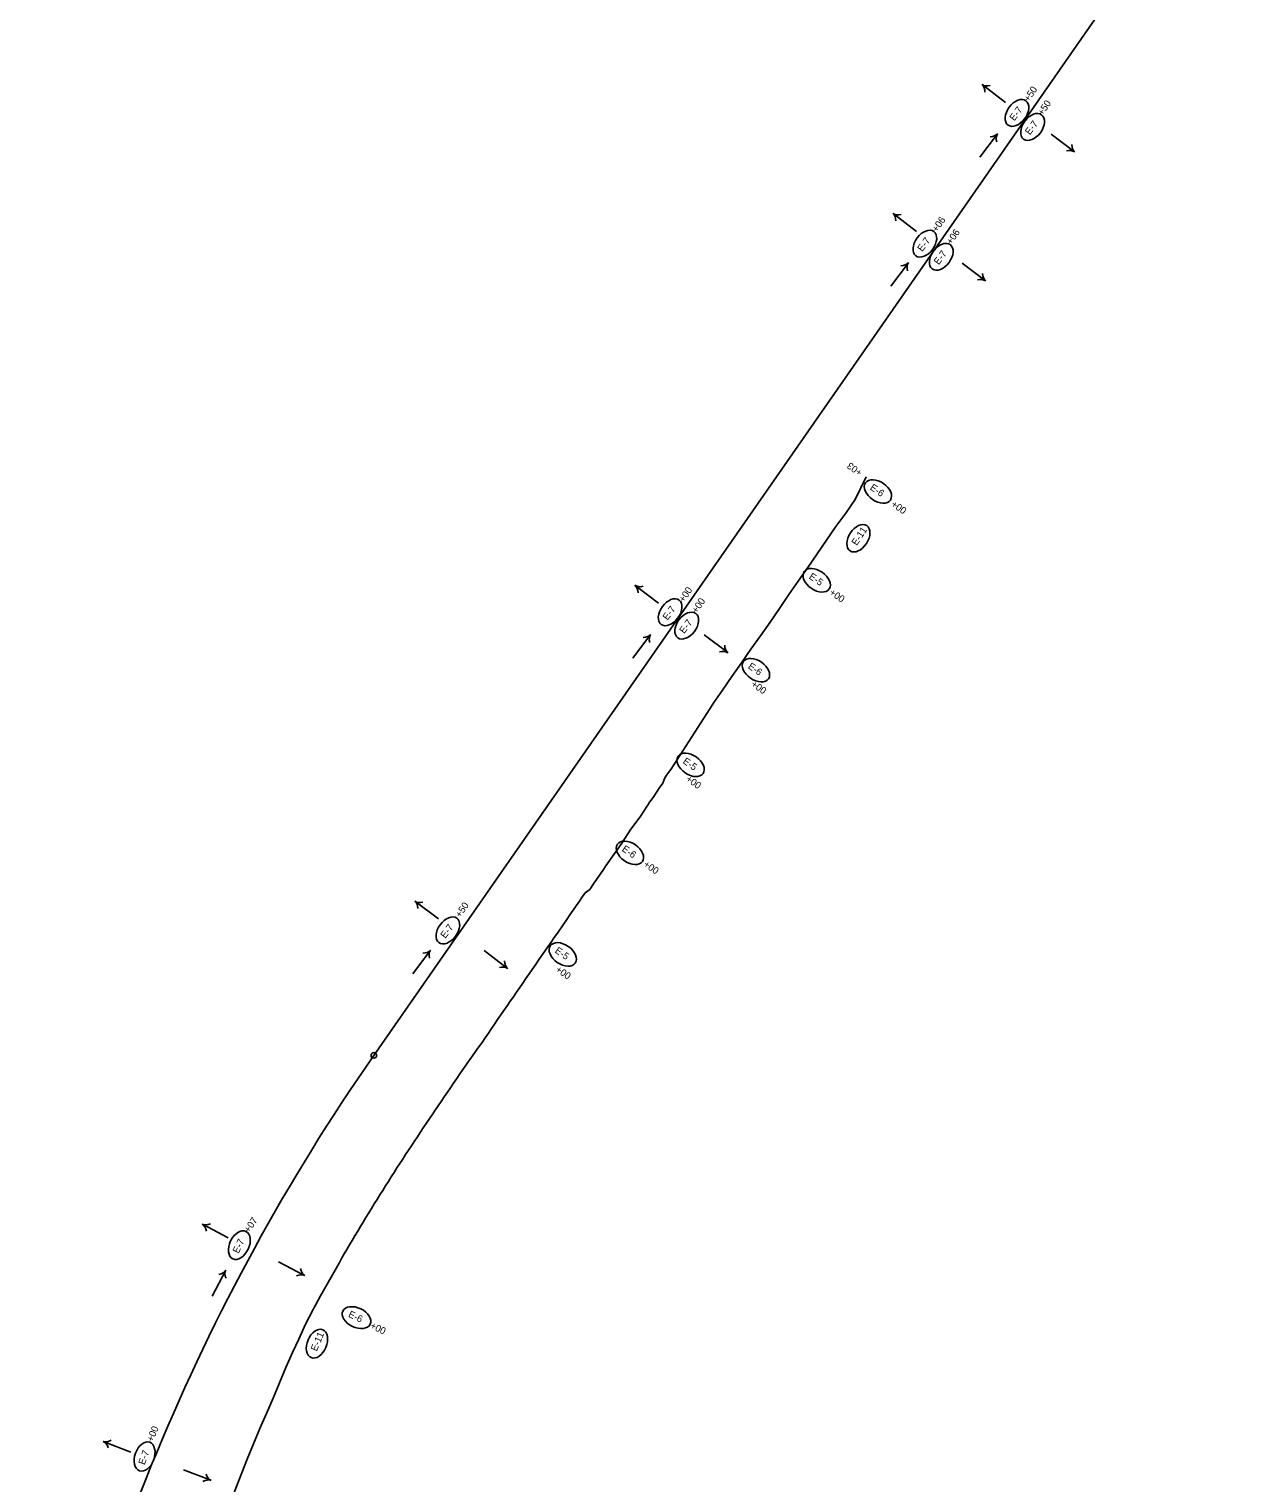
# Model space of a CAD drawing. Extents: x 669236 to 673912, y 735758 to 754788.
# Drawn here: x 671260 to 672351, y 745505 to 746819 of the extents above; entities that cross this region are included whole.
import ezdxf

# ---------------------------------------------------------------- set-up
doc = ezdxf.new("R2010")
doc.units = 0
for name, color, linetype in [('Default', 7, 'Continuous'), ('Prop_Horiz Alignment', 7, 'Continuous'), ('R_Erosion', 7, 'Continuous'), ('R_Erosion_2', 7, 'Continuous'), ('R_Erosion_3', 7, 'Continuous'), ('R_Flow Arrows', 7, 'Continuous')]:
    doc.layers.add(name, color=color, linetype=linetype)

msp = doc.modelspace()

# ---------------------------------------------------------------- linework, layer by layer
at = {"layer": 'Default'}
msp.add_line((671572, 745891.2), (673440.9, 748577.2), dxfattribs=at)
msp.add_arc((673139.7, 744800.4), 1909.9, 145.1701, 169.7611, dxfattribs=at)
at = {"layer": 'Prop_Horiz Alignment'}
msp.add_circle((671572, 745891.2), 2.5, dxfattribs=at)
at = {"layer": 'R_Erosion'}
for p, q in [((671833.2, 746137.3), (671835.1, 746142.2)), ((671760.6, 746034.8), (671762.9, 746038.2))]:
    msp.add_line(p, q, dxfattribs=at)
for points in [[(671878.8, 746209.3), (671887.2, 746221.4), (671895.8, 746233.7), (671904.4, 746246), (671912.9, 746258.3), (671921.6, 746270.6), (671930.2, 746282.8), (671938.9, 746295.1), (671947.2, 746307.7), (671955.7, 746320), (671964.4, 746332.2), (671972.9, 746344.6), (671981.3, 746357), (671989.7, 746369.3), (671998.7, 746381.4), (672007.2, 746393.8), (672017.1, 746414.1)], [(671835.1, 746142.2), (671837.5, 746145.6), (671840.4, 746149.8), (671843.2, 746154), (671846, 746158.2), (671848.7, 746162.4), (671851.5, 746166.6), (671854.2, 746170.8), (671856.9, 746175), (671859.6, 746179.3), (671862.3, 746183.5), (671865, 746187.7), (671867.7, 746191.9), (671870.4, 746196.1), (671873.1, 746200.3), (671878.5, 746208.8), (671878.8, 746209.3)], [(671762.9, 746038.2), (671767.2, 746041.2), (671770.6, 746046.2), (671773.4, 746050.3), (671778.9, 746058.5), (671781.8, 746062.5), (671787.6, 746070.8), (671790.4, 746074.9), (671796.1, 746083.2), (671798.9, 746087.3), (671801.7, 746091.5), (671804.4, 746095.6), (671807.3, 746099.5), (671813.3, 746107.7), (671816.2, 746111.9), (671821.6, 746120.3), (671824.4, 746124.4), (671827.2, 746128.5), (671830.1, 746132.7), (671833.2, 746137.3)], [(671517.6, 745662.6), (671519.3, 745665.3), (671521.6, 745669.8), (671523.8, 745673.9), (671526.2, 745678), (671528.6, 745682.2), (671531, 745686.4), (671533.4, 745690.6), (671535.8, 745694.9), (671538.1, 745699.1), (671540.5, 745703.3), (671542.8, 745707.5), (671545, 745711.7), (671547.5, 745715.7), (671550, 745719.9), (671552.4, 745724), (671554.9, 745728.2), (671557.4, 745732.3), (671559.8, 745736.4), (671562.3, 745740.5), (671564.8, 745744.7), (671567.3, 745748.8), (671569.8, 745752.8), (671572.4, 745756.9), (671574.9, 745761), (671577.4, 745765.1), (671580, 745769.1), (671582.6, 745773.2), (671585.2, 745777.3), (671587.7, 745781.5), (671590.2, 745785.5), (671592.7, 745789.5), (671595.4, 745793.5), (671598.1, 745797.5), (671600.7, 745801.5), (671603.4, 745805.6), (671606.1, 745809.6), (671608.7, 745813.6), (671611.4, 745817.6), (671614, 745821.6), (671616.7, 745825.6), (671619.4, 745829.6), (671622.1, 745833.6), (671624.8, 745837.6), (671627.5, 745841.6), (671630.2, 745845.5), (671632.9, 745849.6), (671635.7, 745853.7), (671638.5, 745857.9), (671641.3, 745862), (671644.1, 745866.2), (671646.9, 745870.3), (671649.7, 745874.4), (671652.5, 745878.5), (671655.3, 745882.6), (671658.2, 745886.7), (671661.1, 745890.7), (671664, 745894.8), (671666.9, 745898.9), (671669.8, 745903), (671672.6, 745907.1), (671675.5, 745911.2), (671678.3, 745915.4), (671681.1, 745919.5), (671683.9, 745923.7), (671686.8, 745927.8), (671689.6, 745931.9), (671692.4, 745936), (671695.2, 745940.1), (671698.2, 745944.1), (671701.1, 745948.3), (671703.9, 745952.5), (671706.6, 745956.6), (671709.4, 745960.7), (671712.3, 745964.8), (671715.1, 745968.9), (671718, 745973), (671720.8, 745977.2), (671723.6, 745981.3), (671726.5, 745985.4), (671729.3, 745989.5), (671732.2, 745993.6), (671735.1, 745997.7), (671737.9, 746001.8), (671743.7, 746010), (671746.5, 746014.1), (671749.3, 746018.3), (671752.2, 746022.4), (671755, 746026.5), (671757.8, 746030.6), (671760.6, 746034.8)], [(671431.6, 745458.5), (671436.7, 745471.9), (671442, 745485.9), (671447.3, 745500), (671452.6, 745513.9), (671457.5, 745526.2), (671463.1, 745540.1), (671469, 745553.8), (671475, 745567.6), (671480.8, 745581.5), (671486.6, 745595.3), (671492.4, 745609.1), (671498.5, 745622.7), (671504, 745634.7), (671510.1, 745648.3), (671517, 745661.5), (671517.6, 745662.6)]]:
    msp.add_lwpolyline(points, dxfattribs=at)
for centre, major_axis in [((672010.1, 746358.7), (7.5, 11.4)), ((671520.5, 745630.6), (5.3, 12.6))]:
    msp.add_ellipse(centre, major_axis=major_axis, ratio=0.638788, dxfattribs=at)
at = {"layer": 'R_Erosion_2'}
for centre, major_axis in [((672153.5, 746743.2), (8.1, 11)), ((672167.6, 746730.5), (8.1, 11)), ((672070.2, 746625), (8.1, 11)), ((672085, 746613.1), (8.1, 11)), ((671839.9, 746291.8), (8.1, 11)), ((671854.9, 746279.7), (8.1, 11)), ((671638.9, 746004.2), (8.1, 11)), ((671450.4, 745719.7), (5.9, 12.4)), ((671364.7, 745528.6), (4.6, 12.9))]:
    msp.add_ellipse(centre, major_axis=major_axis, ratio=0.638788, dxfattribs=at)
at = {"layer": 'R_Erosion_3'}
for centre, major_axis in [((672027.8, 746401), (11.3, -7.8)), ((671972.4, 746320.7), (11.3, -7.8)), ((671917.5, 746239.4), (11.3, -7.8)), ((671858.4, 746153.8), (11.3, -7.8)), ((671803.5, 746074.3), (11.3, -7.8)), ((671742.8, 745982.5), (11.3, -7.8)), ((671556.3, 745654.2), (12.4, -5.9))]:
    msp.add_ellipse(centre, major_axis=major_axis, ratio=0.638788, dxfattribs=at)
at = {"layer": 'R_Flow Arrows'}
for p, q in [((672121.9, 746768.8), (672143.1, 746752.7)), ((672135.9, 746724.4), (672120, 746703.1)), ((672205.6, 746708), (672184.5, 746724.1)), ((672041.4, 746652.2), (672062.5, 746636.1)), ((672055.3, 746607.8), (672039.4, 746586.5)), ((672125, 746591.4), (672103.9, 746607.5)), ((671808.2, 746316.1), (671829.4, 746300)), ((671822.2, 746271.7), (671806.3, 746250.4)), ((671891.9, 746255.3), (671870.7, 746271.4)), ((671609.1, 746030.6), (671630.3, 746014.6)), ((671623.1, 745986.2), (671607.2, 745965)), ((671692.8, 745969.9), (671671.7, 745985.9)), ((671416.9, 745738.6), (671440.4, 745726.2)), ((671509.4, 745692.3), (671485.9, 745704.7)), ((671438, 745697.1), (671425.7, 745673.5)), ((671327.3, 745542.2), (671352.1, 745532.6)), ((671424.6, 745507.1), (671399.8, 745516.7))]:
    msp.add_line(p, q, dxfattribs=at)
for centre, major_axis, start_param, end_param in [((672109.4, 746753), (12.2, 16), 5.662936, 6.259934), ((672133.9, 746785), (-12.2, -16), 0.023252, 0.620249), ((672120, 746736.8), (16.1, -12.1), 5.662936, 6.259934), ((672152.2, 746712.5), (-16.1, 12.1), 0.023252, 0.620249), ((672218.2, 746723.7), (-12.2, -16), 5.662936, 6.259934), ((672193.6, 746691.8), (12.2, 16), 0.023252, 0.620249), ((672028.8, 746636.5), (12.2, 16), 5.662936, 6.259934), ((672053.4, 746668.4), (-12.2, -16), 0.023252, 0.620249), ((672039.4, 746620.2), (16.1, -12.1), 5.662936, 6.259934), ((672071.6, 746596), (-16.1, 12.1), 0.023252, 0.620249), ((672113, 746575.2), (12.2, 16), 0.023252, 0.620249), ((672137.6, 746607.2), (-12.2, -16), 5.662936, 6.259934), ((671795.7, 746300.3), (12.2, 16), 5.662936, 6.259934), ((671820.2, 746332.3), (-12.2, -16), 0.023252, 0.620249), ((671806.3, 746284.1), (16.1, -12.1), 5.662936, 6.259934), ((671838.5, 746259.8), (-16.1, 12.1), 0.023252, 0.620249), ((671879.9, 746239.1), (12.2, 16), 0.023252, 0.620249), ((671904.4, 746271.1), (-12.2, -16), 5.662936, 6.259934), ((671596.6, 746014.9), (12.2, 16), 5.662936, 6.259934), ((671621.1, 746046.8), (-12.2, -16), 0.023252, 0.620249), ((671607.2, 745998.7), (16.1, -12.1), 5.662936, 6.259934), ((671639.4, 745974.4), (-16.1, 12.1), 0.023252, 0.620249), ((671705.4, 745985.6), (-12.2, -16), 5.662936, 6.259934), ((671680.8, 745953.7), (12.2, 16), 0.023252, 0.620249), ((671407.1, 745721), (9.4, 17.8), 5.662936, 6.259934), ((671426.1, 745756.5), (-9.4, -17.8), 0.023252, 0.620249), ((671420.3, 745706.7), (17.9, -9.3), 5.662936, 6.259934), ((671456, 745688), (-17.9, 9.3), 0.023252, 0.620249), ((671500.2, 745674.3), (9.4, 17.8), 0.023252, 0.620249), ((671519.2, 745709.9), (-9.4, -17.8), 5.662936, 6.259934), ((671319.7, 745523.6), (7.3, 18.8), 5.662936, 6.259934), ((671334.4, 745561.1), (-7.3, -18.8), 0.023252, 0.620249), ((671417.6, 745488.2), (7.3, 18.8), 0.023252, 0.620249), ((671432.3, 745525.7), (-7.3, -18.8), 5.662936, 6.259934)]:
    msp.add_ellipse(centre, major_axis=major_axis, ratio=0.5625, start_param=start_param, end_param=end_param, dxfattribs=at)

# ---------------------------------------------------------------- texts
at = {"layer": 'R_Erosion'}
for s, rotation, p in [('+03', 144.0227, (672014.2, 746419.4)), ('E-11', 56.615, (672008.6, 746351.6)), ('E-11', 67.0325, (671520.3, 745623.3))]:
    msp.add_text(s, height=6.25, rotation=rotation, dxfattribs=at).set_placement(p)
at = {"layer": 'R_Erosion_2'}
for s, rotation, p in [('+50', 55.5768, (672164.2, 746752.8)), ('+50', 55.5768, (672176.7, 746740.3)), ('E-7', 53.5441, (672151.1, 746735.5)), ('E-7', 53.5441, (672165.2, 746722.8)), ('+06', 55.5768, (672081.2, 746634.9)), ('+06', 55.5768, (672094.2, 746623.7)), ('E-7', 53.5441, (672067.8, 746617.3)), ('E-7', 53.5441, (672082.7, 746605.4)), ('+00', 55.5768, (671852.3, 746300.3)), ('+00', 55.5768, (671864, 746290.3)), ('E-7', 53.5441, (671837.5, 746284.1)), ('E-7', 53.5441, (671852.6, 746272)), ('+50', 55.5768, (671650.2, 746015.3)), ('E-7', 53.5441, (671636.6, 745996.5)), ('+07', 55.5768, (671459.2, 745730.4)), ('E-7', 64.5405, (671449.6, 745711.7)), ('+00', 67.3885, (671372.1, 745541.4)), ('E-7', 70.3122, (671364.7, 745520.6))]:
    msp.add_text(s, height=6.25, rotation=rotation, dxfattribs=at).set_placement(p)
at = {"layer": 'R_Erosion_3'}
for s, rotation, p in [('E-6', 325.2794, (672020, 746403.2)), ('+00', 325.4451, (672039.1, 746388.1)), ('E-5', 325.2794, (671964.8, 746322.7)), ('+00', 325.4451, (671983.3, 746308.3)), ('E-6', 325.2794, (671909.7, 746241.6)), ('+00', 325.4451, (671912.5, 746225.4)), ('E-5', 325.2794, (671850.8, 746155.8)), ('+00', 325.4451, (671853.5, 746139.7)), ('E-6', 325.2794, (671795.7, 746076.5)), ('+00', 325.4451, (671815.2, 746062.6)), ('E-5', 325.2794, (671735.1, 745984.6)), ('+00', 325.4451, (671735.7, 745967.5)), ('E-6', 334.4934, (671548.3, 745655.1)), ('+00', 334.6591, (671568.1, 745644.8))]:
    msp.add_text(s, height=6.25, rotation=rotation, dxfattribs=at).set_placement(p)

doc.saveas('drawing.dxf')
